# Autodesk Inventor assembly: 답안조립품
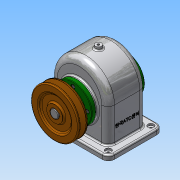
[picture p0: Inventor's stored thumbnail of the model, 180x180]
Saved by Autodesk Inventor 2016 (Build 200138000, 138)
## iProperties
Created: 2018-08
Part Number: 답안조립품
Material: 일반
Document SubType Name: Assembly
Designer: Administrator
Author: Administrator
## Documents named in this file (14)
- C:\Users\Administrator\Desktop\480811V1008\답안조립품.iam
- C:\Users\Administrator\Desktop\480811V1008\본체.ipt
- C:\Users\Administrator\Desktop\480811V1008\축.ipt
- C:\Users\Administrator\Desktop\480811V1008\베어링 6203.ipt
- C:\Users\Administrator\Desktop\480811V1008\키 6x6x22.ipt
- C:\Users\Administrator\Desktop\480811V1008\스퍼기어.ipt
- C:\Users\Administrator\Desktop\480811V1008\뒤커버.ipt
- C:\Users\Administrator\Desktop\480811V1008\부시.ipt
- C:\Users\Administrator\Desktop\480811V1008\앞커버.ipt
- C:\Users\Administrator\Desktop\480811V1008\오일 실 28 40 8.ipt
- C:\Users\Administrator\Desktop\480811V1008\키 5x5x18.ipt
- C:\Users\Administrator\Desktop\480811V1008\V-벨트풀리.ipt
- C:\Users\Administrator\Desktop\480811V1008\멈춤나사 M4.ipt
- C:\Users\Administrator\Desktop\480811V1008\볼트 M4.ipt
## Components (1 placed, 1 different names)
1. V-벨트풀리:1
